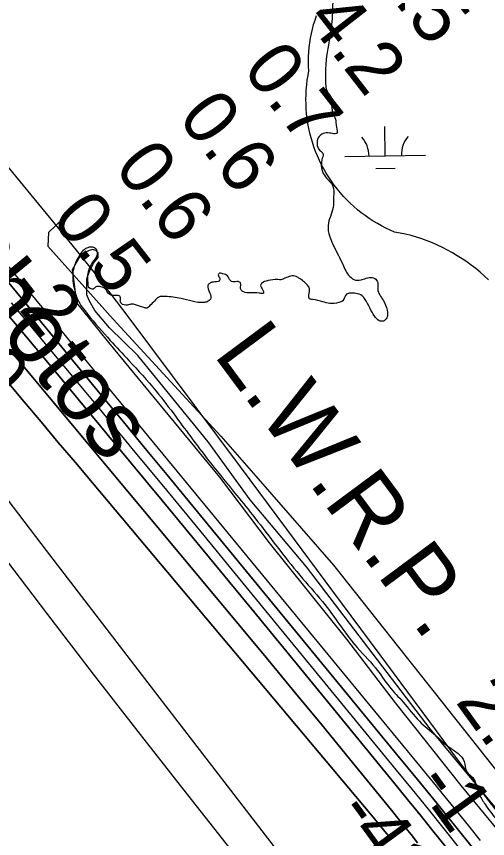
# Model space of a CAD drawing. Extents: x 3887375 to 3925618, y 296674 to 322633.
# Drawn here: x 3902961 to 3903543, y 304360 to 305377 of the extents above; entities that cross this region are included whole.
import ezdxf

# ---------------------------------------------------------------- set-up
doc = ezdxf.new("R2010")
doc.units = 0
for name, color, linetype in [('V-RIVR-EDGE', 7, 'Continuous'), ('V-RIVR-IDEN', 7, 'Continuous'), ('V-RIVR-JETY', 7, 'Continuous'), ('V-RIVR-RANG', 7, 'Continuous'), ('V-RRAP-FSHR', 7, 'Continuous'), ('V-TOPO-DPTH', 7, 'Continuous'), ('V-TOPO-MAJR', 7, 'Continuous'), ('V-TOPO-MINR', 7, 'Continuous'), ('V-TOPO-WATR', 7, 'Continuous'), ('V-TOPO-WATR-IDEN', 7, 'Continuous'), ('V-WETL-SWMP', 7, 'Continuous')]:
    doc.layers.add(name, color=color, linetype=linetype)

msp = doc.modelspace()

# ---------------------------------------------------------------- linework, layer by layer
at = {"layer": 'V-RIVR-EDGE'}
for points in [[(3902176.1, 306371.6), (3902185, 306369.6), (3902189.7, 306365.9), (3902193.6, 306361.3), (3902196.3, 306361.6), (3902200.6, 306361.9), (3902204.3, 306360.9), (3902204.3, 306357.2), (3902207.3, 306355.6), (3902212.9, 306354.6), (3902217.3, 306359.2), (3902217.3, 306360.5), (3902213.9, 306363.5), (3902204.6, 306365.9), (3902201.3, 306370.2), (3902201.3, 306373.6), (3902205.7, 306381.2), (3902209, 306387.2), (3902211.7, 306394.8), (3902215, 306395.8), (3902221, 306396.4), (3902222, 306399.8), (3902220.7, 306414.7), (3902221.1, 306419.4), (3902225.4, 306424.4), (3902235.1, 306431.3), (3902247, 306436.6), (3902261.7, 306439.6), (3902272.3, 306437.9), (3902296.6, 306433.2), (3902307.2, 306432.8), (3902316.2, 306434.8), (3902320.2, 306439.4), (3902328.5, 306449.1), (3902337.9, 306464.7), (3902350.2, 306483.9), (3902359.2, 306492.2), (3902372.6, 306502.5), (3902375.2, 306502.5), (3902376.9, 306498.8), (3902382.5, 306484.2), (3902385.5, 306480.5), (3902388.5, 306484.5), (3902395.2, 306492.1), (3902402.2, 306498.1), (3902406.5, 306498.1), (3902416.4, 306494.7), (3902425.7, 306492.7), (3902437, 306489), (3902445.3, 306479.7), (3902451, 306477), (3902457.3, 306474), (3902462.6, 306472), (3902470.2, 306468), (3902482.5, 306458.3), (3902494.5, 306448), (3902501.8, 306438.3), (3902514, 306428.3), (3902524, 306421), (3902532.6, 306417.3), (3902535.6, 306415.3), (3902527.9, 306397.7), (3902521.6, 306372.8), (3902519.5, 306360.1), (3902521.5, 306352.8), (3902521.8, 306344.8), (3902522.1, 306341.8), (3902524.1, 306339.2), (3902527.5, 306337.8), (3902534.1, 306337.5), (3902538.4, 306337.1), (3902544.1, 306335.1), (3902544.1, 306328.5), (3902550, 306324.1), (3902556.3, 306322.5), (3902561.7, 306323.1), (3902565, 306325.8), (3902570, 306331.4), (3902572, 306338.1), (3902571.7, 306347), (3902569.1, 306353.7), (3902571.4, 306357.7), (3902575.4, 306360.3), (3902579.1, 306361.3), (3902585, 306359), (3902592.7, 306351.3), (3902593, 306344.6), (3902587.3, 306334.7), (3902586.3, 306329.4), (3902585.9, 306322.7), (3902585.6, 306318.1), (3902584.3, 306315.7), (3902576.9, 306316.4), (3902574.9, 306314.8), (3902570.3, 306307.1), (3902569.3, 306302.1), (3902570.6, 306294.5), (3902573.9, 306286.5), (3902577.5, 306281.5), (3902577.2, 306273.5), (3902576.8, 306261.9), (3902576.8, 306255.9), (3902580.1, 306248.6), (3902588.1, 306240.9), (3902593, 306234.6), (3902597.7, 306226.6), (3902598.6, 306211.6), (3902599.6, 306207.6), (3902602.9, 306206.6), (3902607.6, 306205.6), (3902613.2, 306202.9), (3902623.5, 306192.6), (3902623.8, 306183), (3902620.8, 306150), (3902617.1, 306141.7), (3902604.4, 306129.5), (3902600.8, 306128.8), (3902599.1, 306130.8), (3902593.8, 306134.8), (3902592.1, 306134.5), (3902588.1, 306132.8), (3902583.1, 306122.9), (3902581.8, 306112.9), (3902576.8, 306107.3), (3902571.4, 306106.3), (3902567.1, 306105.6), (3902564.8, 306102.3), (3902562.8, 306096), (3902564.4, 306088.7), (3902565.1, 306077.7), (3902563, 306067.4), (3902556.4, 306058.1), (3902540, 306049.2), (3902533, 306041.5), (3902530, 306032.2), (3902526, 306031.2), (3902511.7, 306032.3), (3902507.7, 306031.9), (3902504.1, 306028.6), (3902498.1, 306024.3), (3902498.1, 306022.7), (3902499.4, 306019.7), (3902509.7, 306013), (3902517, 306003), (3902523.3, 305984.4), (3902524.9, 305962.4), (3902516.8, 305945.5), (3902499.8, 305928.2), (3902495.2, 305921.6), (3902491.8, 305915.3), (3902491.5, 305907.9), (3902495.1, 305898), (3902507.7, 305881.6), (3902519, 305871), (3902537.2, 305860), (3902548.9, 305856.6), (3902563.1, 305845.3), (3902578.7, 305830.6), (3902592.7, 305812.9), (3902609.9, 305797.9), (3902620.5, 305791.2), (3902627.5, 305791.6), (3902638.2, 305797.8), (3902653.2, 305812.1), (3902657.9, 305821.4), (3902666.2, 305828.7), (3902675.2, 305837.7), (3902677.5, 305839.7), (3902680.9, 305839.3), (3902680.8, 305837.3), (3902674.8, 305825), (3902672.8, 305820), (3902672.8, 305811.7), (3902671.8, 305803.1), (3902668.4, 305797.8), (3902666.1, 305790.8), (3902666.8, 305785.8), (3902670.4, 305780.8), (3902675.7, 305776.1), (3902679, 305767.2), (3902680.7, 305758.8), (3902685.3, 305754.2), (3902689.6, 305753.2), (3902695.6, 305752.8), (3902700.9, 305748.1), (3902702.9, 305740.2), (3902701.5, 305733.8), (3902694.5, 305721.2), (3902692.2, 305715.6), (3902692.2, 305711.6), (3902693.1, 305701.6), (3902699.4, 305695.3), (3902708.1, 305687.3), (3902714.4, 305676.6), (3902720, 305665.6), (3902725.6, 305651.3), (3902730.9, 305645.3), (3902741.9, 305639), (3902754.8, 305636.6), (3902765.1, 305633.3), (3902768.8, 305628.9), (3902768.8, 305618), (3902768.7, 305611), (3902772.7, 305603.3), (3902781.7, 305599.6), (3902789, 305599.3), (3902796, 305603.6), (3902803, 305605.6), (3902808.3, 305603.9), (3902808.3, 305598.9), (3902804.9, 305594.3), (3902804.9, 305590.3), (3902807.6, 305587.9), (3902817.6, 305583.9), (3902819.6, 305586.2), (3902819.6, 305590.9), (3902821.2, 305591.9), (3902832.5, 305592.5), (3902842.5, 305596.8), (3902852.5, 305597.1), (3902854.8, 305594.8), (3902857.8, 305588.1), (3902865.4, 305585.1), (3902874.1, 305584.8), (3902880.4, 305584.8), (3902884.4, 305580.8), (3902889.7, 305574.1), (3902894.3, 305573.4), (3902905.3, 305571.7), (3902914.3, 305567.1), (3902916.9, 305564.1), (3902916.9, 305558.7), (3902913.2, 305551.8), (3902914.2, 305547.8), (3902915.6, 305542.8), (3902919.5, 305539.8), (3902947.8, 305531.4), (3902977.7, 305524), (3902984.3, 305525), (3902990, 305526.6), (3902996, 305526.3), (3903002, 305519.6), (3903010.9, 305512.6), (3903019.9, 305512.3), (3903025.9, 305511.9), (3903032.2, 305512.2), (3903042.2, 305508.9), (3903061.4, 305496.9), (3903085.3, 305489.1), (3903128.2, 305479.4), (3903164.8, 305476), (3903184.4, 305477.6), (3903213.4, 305483.5), (3903240.3, 305495.1), (3903274, 305520.9), (3903309.3, 305542.8), (3903337.6, 305555), (3903351.2, 305558.3), (3903361.2, 305558.3), (3903371.2, 305555.3), (3903391.7, 305535.6), (3903408, 305512.6), (3903409.6, 305502.3), (3903410.6, 305494.3), (3903401.6, 305487.7), (3903390.2, 305472.1), (3903369.9, 305431.9), (3903356.5, 305407), (3903353.5, 305400), (3903351.8, 305393.4), (3903351.5, 305385.7), (3903349, 305356.1), (3903343.3, 305318.6), (3903342.9, 305298), (3903346.2, 305282), (3903350.8, 305274), (3903350.2, 305270), (3903350.8, 305263.4), (3903351.8, 305257.7), (3903355.1, 305250.1), (3903356.4, 305240.1), (3903356.4, 305232.4), (3903353.4, 305232.1), (3903345.8, 305233.1), (3903338.4, 305231.5), (3903333.8, 305226.8), (3903332.4, 305219.8), (3903335.7, 305211.5), (3903340, 305206.9), (3903339.4, 305203.5), (3903338, 305197.2), (3903338.3, 305187.6), (3903343, 305178.6), (3903351.9, 305167.3), (3903352.9, 305154), (3903352.2, 305140.7), (3903346.1, 305118.7), (3903353.1, 305092.8), (3903364.3, 305070.5), (3903372.9, 305055.5), (3903379.9, 305051.1), (3903389.5, 305052.1), (3903403.8, 305053.1), (3903407.5, 305048.1), (3903407.5, 305039.8), (3903414.1, 305026.1), (3903419, 305013.8), (3903419, 305005.1), (3903416.7, 305001.8), (3903413.7, 305000.2), (3903409.4, 305000.8), (3903403.7, 305006.2), (3903391.8, 305027.2), (3903388.2, 305031.5), (3903380.5, 305034.5), (3903373.9, 305034.9), (3903368.9, 305033.5), (3903364.2, 305025.6), (3903359.2, 305023.3), (3903348.2, 305022.3), (3903339.6, 305024.3), (3903327, 305027), (3903323.3, 305028), (3903322.3, 305032.7), (3903323, 305040.6), (3903320.7, 305044.6), (3903310.1, 305053.6), (3903306.7, 305055.6), (3903292.8, 305053.3), (3903287.8, 305051.4), (3903283.8, 305051.7), (3903271.8, 305050.4), (3903263.8, 305046.8), (3903262.8, 305045.4), (3903264.5, 305040.1), (3903266.1, 305034.8), (3903261.8, 305034.8), (3903247.8, 305035.2), (3903239.9, 305037.5), (3903237.9, 305040.8), (3903237.9, 305047.5), (3903234.9, 305049.2), (3903228.2, 305048.9), (3903225.3, 305050.5), (3903221.6, 305056.2), (3903216, 305058.9), (3903211, 305058.9), (3903210.3, 305057.5), (3903212.3, 305052.9), (3903211.6, 305049.9), (3903208.3, 305048.9), (3903200.6, 305047.6), (3903197.6, 305044.6), (3903199.9, 305035), (3903200.6, 305027.6), (3903196.6, 305024.3), (3903191.9, 305023.3), (3903164.3, 305028.4), (3903144.7, 305030.8), (3903136.8, 305030.1), (3903131.4, 305025.1), (3903125.8, 305019.5), (3903121.8, 305016.5), (3903118.1, 305017.2), (3903108.1, 305020.5), (3903102.5, 305021.2), (3903098.2, 305020.2), (3903090.5, 305022.3), (3903089.2, 305025.9), (3903089.2, 305030.2), (3903087.9, 305031.6), (3903081.6, 305031.9), (3903074.6, 305034.6), (3903070.6, 305040.3), (3903065, 305042.9), (3903059, 305042.6), (3903055.6, 305040), (3903050.7, 305041.6), (3903049.3, 305047.6), (3903049.4, 305059.6), (3903055.1, 305073.2), (3903060.7, 305081.9), (3903060.7, 305086.5), (3903057.8, 305090.5), (3903052.4, 305091.8), (3903045.8, 305089.5), (3903036.4, 305077.9), (3903031.1, 305064.3), (3903030.4, 305053.3), (3903032, 305041.4), (3903036.6, 305026.7), (3903048.6, 305009.1), (3903076.8, 304976.4)], [(3903076.8, 304976.4), (3903099.6, 304951.7), (3903133.5, 304913.7), (3903157.3, 304882.8), (3903201.1, 304824.5), (3903232.9, 304785.1), (3903255.5, 304757.1), (3903311.1, 304686.2), (3903339, 304653.5), (3903361.5, 304623.5), (3903379.1, 304600.2), (3903404.6, 304571.6), (3903422.2, 304547.9), (3903438.8, 304529.2), (3903459, 304505.6), (3903478.9, 304488.2), (3903495.2, 304473.9), (3903506.8, 304465.6), (3903514.4, 304455.6), (3903517.7, 304442.9), (3903525, 304435.9), (3903528, 304430.3), (3903533.3, 304414.6), (3903540.6, 304402.3), (3903553.8, 304385), (3903573.4, 304364.3), (3903587.6, 304346.3), (3903597.9, 304330), (3903605.9, 304324), (3903619.5, 304318), (3903629.1, 304317.6), (3903632.8, 304318.3), (3903633.1, 304320.9), (3903633.5, 304324.3), (3903630.5, 304325.9), (3903622.8, 304326.6), (3903615.5, 304329.9), (3903606.2, 304338.3), (3903597.6, 304350.3), (3903589.3, 304364.3), (3903583.7, 304377.9), (3903578.4, 304391.9), (3903578.4, 304392.9), (3903580.1, 304393.2), (3903589.4, 304383.2), (3903599.7, 304368.6), (3903605.3, 304364.9), (3903612.6, 304364.2), (3903629.3, 304364.8), (3903634.2, 304366.5), (3903638.2, 304368.1), (3903639.3, 304373.8), (3903643.6, 304377.4), (3903648.9, 304379.1), (3903661.2, 304376.4), (3903666.5, 304381.4), (3903670.9, 304383.3), (3903678.8, 304383), (3903682.5, 304380.3), (3903681.5, 304372.3), (3903684.5, 304369.3), (3903690.1, 304365), (3903701.4, 304362), (3903712.4, 304361.6), (3903722, 304361.9), (3903727, 304360.6), (3903733, 304354.3), (3903743.6, 304342.3), (3903751.2, 304323), (3903759.5, 304308.6), (3903773.7, 304295.6), (3903789, 304280.3), (3903789.3, 304273.7), (3903788.3, 304266.7), (3903788.6, 304258), (3903792.2, 304248), (3903804.2, 304230.1), (3903817.7, 304208.1), (3903825.4, 304197.7), (3903828.4, 304195.1), (3903832.7, 304194.4), (3903838, 304199.4), (3903840, 304194.7), (3903840.6, 304188.7), (3903836.6, 304174.4), (3903836.3, 304162.1), (3903833.9, 304151.2), (3903823.2, 304132.6), (3903817.9, 304125.6), (3903807.2, 304122.3), (3903805.2, 304120.6), (3903803.2, 304116), (3903802.8, 304100.7), (3903801.2, 304098.7), (3903799.5, 304102), (3903789.9, 304117.7), (3903782.3, 304126.7), (3903774.7, 304132), (3903768, 304139), (3903763.1, 304152.3), (3903763.1, 304158), (3903770.8, 304167)]]:
    msp.add_spline(points, degree=3, dxfattribs=at)
at = {"layer": 'V-RIVR-JETY'}
msp.add_lwpolyline([(3903654.5, 304276.3), (3903472.4, 304496.3), (3903319.6, 304696.6), (3903249.6, 304779.3), (3903197.8, 304851.1), (3903110.9, 304957.6), (3903075.9, 304992.2), (3903057.6, 305013.3), (3903050.6, 305025.9), (3903047.8, 305032.9), (3903047.8, 305046.9), (3903047.8, 305052.5), (3903050.6, 305060.9), (3903056.2, 305072.1), (3903061.8, 305079.1), (3903061.8, 305084.7), (3903059, 305087.5), (3903054.8, 305088.9), (3903050.6, 305087.5), (3903040.8, 305083.3), (3903029.6, 305063.7), (3903032.4, 305042.7), (3903035.2, 305023.1), (3903050.6, 305003.5), (3903074.5, 304974), (3903105.3, 304936.2), (3903211.8, 304807.3), (3903273.4, 304726), (3903368.7, 304606.9), (3903428.9, 304528.5), (3903510.2, 304426.2), (3903608.3, 304307.1)], dxfattribs=at)
at = {"layer": 'V-RRAP-FSHR'}
msp.add_lwpolyline([(3903045.7, 305153), (3903000.5, 305110.1), (3902999.7, 305092.9), (3903080.3, 305002.7), (3903213.4, 304858.1), (3903256.6, 304808.5), (3903352.6, 304698.4), (3903593.7, 304394.4), (3903689.6, 304280), (3903700.5, 304276.3), (3903747.8, 304312.8)], dxfattribs=at)
at = {"layer": 'V-TOPO-DPTH'}
for points in [[(3903859.2, 304002.2), (3903567.5, 304378.2), (3903545.4, 304406.9), (3903523.4, 304435.6), (3903501.7, 304464.5), (3903480.1, 304493.5), (3903409.1, 304589.4), (3903352.1, 304666.3), (3903295, 304743.2), (3903237.7, 304820), (3903180.4, 304896.8), (3903098.9, 305005.9), (3903077.9, 305033.5), (3903056.7, 305060.9), (3903035.1, 305088.1), (3903013.2, 305115), (3902805.9, 305366.7)], [(3903527.5, 304345.9), (3903504, 304375.1), (3903480.4, 304404.3), (3903456.7, 304433.4), (3903432.9, 304462.5), (3903146.9, 304810.5), (3903120.1, 304843), (3903093.3, 304875.6), (3903066.5, 304908.1), (3903039.6, 304940.6), (3903036, 304944.9), (3903011, 304975.3), (3902985.9, 305005.6), (3902960.8, 305036), (3902935.7, 305066.3)], [(3902935.7, 305066.3), (3902960.8, 305036), (3902985.9, 305005.6), (3903011, 304975.3), (3903036, 304944.9), (3903039.6, 304940.6), (3903066.5, 304908.1), (3903093.3, 304875.6), (3903120.1, 304843), (3903146.9, 304810.5), (3903432.9, 304462.5), (3903456.7, 304433.4), (3903480.4, 304404.3), (3903504, 304375.1), (3903527.5, 304345.9)], [(3902948.6, 305010.1), (3902965.6, 304989.7), (3902982.5, 304969.4), (3902999.4, 304949), (3903082.6, 304848.9), (3903141, 304778.3), (3903199.3, 304707.8), (3903257.5, 304637), (3903315.6, 304566.2), (3903428.6, 304428.3), (3903444.3, 304408.9), (3903460, 304389.6), (3903475.7, 304370.1), (3903491.3, 304350.7)], [(3902948.6, 305010.1), (3902965.6, 304989.7), (3902982.5, 304969.4), (3902999.4, 304949), (3903082.6, 304848.9), (3903141, 304778.3), (3903199.3, 304707.8), (3903257.5, 304637), (3903315.6, 304566.2), (3903428.6, 304428.3), (3903444.3, 304408.9), (3903460, 304389.6), (3903475.7, 304370.1), (3903491.3, 304350.7)], [(3903456.7, 304355.3), (3903448.7, 304365.4), (3903440.6, 304375.5), (3903432.5, 304385.5), (3903424.4, 304395.5), (3903372.4, 304459.2), (3903338.2, 304501), (3903303.9, 304542.7), (3903269.5, 304584.3), (3903235, 304625.8), (3902961.9, 304953.1), (3902953.4, 304963.3)], [(3902953.4, 304963.3), (3902961.9, 304953.1), (3903235, 304625.8), (3903269.5, 304584.3), (3903303.9, 304542.7), (3903338.2, 304501), (3903372.4, 304459.2), (3903424.4, 304395.5), (3903432.5, 304385.5), (3903440.6, 304375.5), (3903448.7, 304365.4), (3903456.7, 304355.3)], [(3903423.8, 304359.8), (3903422.1, 304362), (3903421.2, 304363.1), (3903420.3, 304364.1), (3903414.6, 304371.2), (3903410.9, 304375.7), (3903407.1, 304380.3), (3903403.4, 304384.9), (3903399.6, 304389.4), (3903054.7, 304800.2), (3903033.6, 304825.3), (3903012.5, 304850.4), (3902991.3, 304875.6), (3902970.2, 304900.7), (3902930.2, 304948)], [(3902930.2, 304948), (3902970.2, 304900.7), (3902991.3, 304875.6), (3903012.5, 304850.4), (3903033.6, 304825.3), (3903054.7, 304800.2), (3903399.6, 304389.4), (3903403.4, 304384.9), (3903407.1, 304380.3), (3903410.9, 304375.7), (3903414.6, 304371.2), (3903420.3, 304364.1), (3903421.2, 304363.1), (3903422.1, 304362), (3903423.8, 304359.8)]]:
    msp.add_lwpolyline(points, dxfattribs=at)
at = {"layer": 'V-TOPO-MAJR'}
msp.add_lwpolyline([(3903314.6, 304305.1), (3903141.4, 304530), (3903093.6, 304592.1), (3903045.8, 304654.3), (3902998.1, 304716.5), (3902950.4, 304778.8)], dxfattribs=at)
at = {"layer": 'V-TOPO-MINR'}
for points in [[(3903534.5, 304358.1), (3903520, 304376.1), (3903505.5, 304394.1), (3903491, 304412.1), (3903476.4, 304429.9), (3903461.7, 304447.8), (3903061.4, 304933.9), (3903050.5, 304947.2), (3903039.6, 304960.5), (3903028.6, 304973.7), (3903017.7, 304986.9), (3903001.3, 305006.8), (3902998.6, 305010.1), (3902995.9, 305013.4), (3902993.2, 305016.7), (3902990.4, 305020.1), (3902584.2, 305513.2)], [(3903527.5, 304345.9), (3903504, 304375.1), (3903480.4, 304404.3), (3903456.7, 304433.4), (3903432.9, 304462.5), (3903146.9, 304810.5), (3903120.1, 304843), (3903093.3, 304875.6), (3903066.5, 304908.1), (3903039.6, 304940.6), (3903036, 304944.9), (3903011, 304975.3), (3902985.9, 305005.6), (3902960.8, 305036), (3902935.7, 305066.3)], [(3903509.2, 304348.3), (3903489.7, 304372.6), (3903470.1, 304396.9), (3903450.4, 304421), (3903430.7, 304445.2), (3903231.6, 304687.9), (3903189.1, 304739.6), (3903146.5, 304791.3), (3903103.9, 304843), (3903061.2, 304894.6), (3903017.8, 304947), (3902996.8, 304972.3), (3902975.8, 304997.7), (3902954.7, 305023.1)], [(3903491.3, 304350.7), (3903475.7, 304370.1), (3903460, 304389.6), (3903444.3, 304408.9), (3903428.6, 304428.3), (3903315.6, 304566.2), (3903257.5, 304637), (3903199.3, 304707.8), (3903141, 304778.3), (3903082.6, 304848.9), (3902999.4, 304949), (3902982.5, 304969.4), (3902965.6, 304989.7), (3902948.6, 305010.1)], [(3903456.7, 304355.3), (3903448.7, 304365.4), (3903440.6, 304375.5), (3903432.5, 304385.5), (3903424.4, 304395.5), (3903372.4, 304459.2), (3903338.2, 304501), (3903303.9, 304542.7), (3903269.5, 304584.3), (3903235, 304625.8), (3902961.9, 304953.1), (3902953.4, 304963.3)], [(3903423.8, 304359.8), (3903422.1, 304362), (3903421.2, 304363.1), (3903420.3, 304364.1), (3903414.6, 304371.2), (3903410.9, 304375.7), (3903407.1, 304380.3), (3903403.4, 304384.9), (3903399.6, 304389.4), (3903054.7, 304800.2), (3903033.6, 304825.3), (3903012.5, 304850.4), (3902991.3, 304875.6), (3902970.2, 304900.7), (3902930.2, 304948)], [(3904127.3, 303194.1), (3904081.2, 303256), (3904035, 303317.7), (3903846.7, 303567.3), (3903832.7, 303585.6), (3903818.6, 303603.9), (3903804.4, 303622.1), (3903790.1, 303640.2), (3903704.2, 303747.7), (3903646.9, 303819.5), (3903589.5, 303891.2), (3903532.2, 303963), (3903474.8, 304034.7), (3903327.7, 304218.3), (3903308.7, 304242.1), (3903289.8, 304265.9), (3903270.9, 304289.7), (3903252.1, 304313.6), (3903172.5, 304414.6), (3903114.1, 304489.1), (3903056.1, 304563.9), (3902998.5, 304639.1), (3902941.2, 304714.5)]]:
    msp.add_lwpolyline(points, dxfattribs=at)
at = {"layer": 'V-TOPO-WATR'}
msp.add_lwpolyline([(3903859.2, 304002.2), (3903567.5, 304378.2), (3903545.4, 304406.9), (3903523.4, 304435.6), (3903501.7, 304464.5), (3903480.1, 304493.5), (3903409.1, 304589.4), (3903352.1, 304666.3), (3903295, 304743.2), (3903237.7, 304820), (3903180.4, 304896.8), (3903098.9, 305005.9), (3903077.9, 305033.5), (3903056.7, 305060.9), (3903035.1, 305088.1), (3903013.2, 305115), (3902805.9, 305366.7)], dxfattribs=at)
at = {"layer": 'V-WETL-SWMP'}
for p, q in [((3903330, 305372.6), (3903331.9, 305378.1)), ((3903326.7, 305361.5), (3903328.2, 305367.1)), ((3903328.2, 305367.1), (3903330, 305372.6)), ((3903325.4, 305355.9), (3903326.7, 305361.5)), ((3903323.4, 305344.5), (3903324.3, 305350.2)), ((3903324.3, 305350.2), (3903325.4, 305355.9)), ((3903322.2, 305333.1), (3903322.7, 305338.8)), ((3903322.7, 305338.8), (3903323.4, 305344.5)), ((3903321.9, 305327.3), (3903322.2, 305333.1)), ((3903321.9, 305321.5), (3903321.9, 305327.3)), ((3903322, 305315.7), (3903321.9, 305321.5)), ((3903321.3, 305304.1), (3903322.4, 305310)), ((3903322.4, 305310), (3903322, 305315.7)), ((3903319.7, 305292.3), (3903320.4, 305298.2)), ((3903320.4, 305298.2), (3903321.3, 305304.1)), ((3903318.8, 305280.3), (3903319.1, 305286.3)), ((3903319.1, 305286.3), (3903319.7, 305292.3)), ((3903318.7, 305274.4), (3903318.8, 305280.3)), ((3903318.8, 305268.4), (3903318.7, 305274.4)), ((3903319.1, 305262.4), (3903318.8, 305268.4)), ((3903319.6, 305256.5), (3903319.1, 305262.4)), ((3903320.3, 305250.5), (3903319.6, 305256.5)), ((3903321.2, 305244.6), (3903320.3, 305250.5)), ((3903322.3, 305238.7), (3903321.2, 305244.6)), ((3903323.6, 305232.9), (3903322.3, 305238.7)), ((3903416.7, 305204.8), (3903416.1, 305240.8)), ((3903325.1, 305227.1), (3903323.6, 305232.9)), ((3903326.8, 305221.4), (3903325.1, 305227.1)), ((3903328.6, 305215.7), (3903326.8, 305221.4)), ((3903330.7, 305210.1), (3903328.6, 305215.7)), ((3903333, 305204.6), (3903330.7, 305210.1)), ((3903335.4, 305199.1), (3903333, 305204.6)), ((3903366.7, 305204), (3903466.7, 305205.7)), ((3903338, 305193.7), (3903335.4, 305199.1)), ((3903340.8, 305188.5), (3903338, 305193.7)), ((3903343.8, 305183.3), (3903340.8, 305188.5)), ((3903405, 305189.2), (3903429, 305189.6)), ((3903347, 305178.2), (3903343.8, 305183.3)), ((3903350.3, 305173.2), (3903347, 305178.2)), ((3903353.8, 305168.4), (3903350.3, 305173.2)), ((3903357.4, 305163.7), (3903353.8, 305168.4)), ((3903361.3, 305159.1), (3903357.4, 305163.7)), ((3903365.2, 305154.6), (3903361.3, 305159.1)), ((3903369.3, 305150.3), (3903365.2, 305154.6)), ((3903373.6, 305146.1), (3903369.3, 305150.3)), ((3903378, 305142), (3903373.6, 305146.1)), ((3903382.5, 305138.1), (3903378, 305142)), ((3903387.2, 305134.4), (3903382.5, 305138.1)), ((3903392, 305130.8), (3903387.2, 305134.4)), ((3903396.9, 305127.4), (3903392, 305130.8)), ((3903401.9, 305124.1), (3903396.9, 305127.4)), ((3903407, 305121), (3903401.9, 305124.1)), ((3903412.2, 305118.1), (3903407, 305121)), ((3903417.5, 305115.4), (3903412.2, 305118.1)), ((3903423, 305112.9), (3903417.5, 305115.4)), ((3903428.4, 305110.5), (3903423, 305112.9)), ((3903435.3, 305109.2), (3903428.4, 305110.5)), ((3903442, 305107.7), (3903435.3, 305109.2)), ((3903448.8, 305106), (3903442, 305107.7)), ((3903455.4, 305104), (3903448.8, 305106)), ((3903462, 305101.9), (3903455.4, 305104)), ((3903468.6, 305099.5), (3903462, 305101.9)), ((3903475, 305097), (3903468.6, 305099.5)), ((3903481.4, 305094.2), (3903475, 305097)), ((3903487.7, 305091.2), (3903481.4, 305094.2)), ((3903493.9, 305088.1), (3903487.7, 305091.2)), ((3903500, 305084.7), (3903493.9, 305088.1)), ((3903505.9, 305081.2), (3903500, 305084.7)), ((3903511.8, 305077.5), (3903505.9, 305081.2)), ((3903517.5, 305073.6), (3903511.8, 305077.5)), ((3903523.2, 305069.5), (3903517.5, 305073.6)), ((3903528.6, 305065.3), (3903523.2, 305069.5)), ((3903534, 305060.8), (3903528.6, 305065.3)), ((3903539.2, 305056.2), (3903534, 305060.8)), ((3903544.3, 305051.5), (3903539.2, 305056.2))]:
    msp.add_line(p, q, dxfattribs=at)
for centre, start, end in [((3903361.5, 305204.3), 0.2115, 41.7552), ((3903472, 305206.2), 140.2115, 181.7552)]:
    msp.add_arc(centre, 35.2, start, end, dxfattribs=at)

# ---------------------------------------------------------------- texts
at = {"layer": 'V-RIVR-IDEN'}
msp.add_text('Aerial    Photos', height=83, rotation=309.2735, dxfattribs=at).set_placement((3902596.7, 305405.2))
at = {"layer": 'V-RIVR-RANG'}
for s, rotation, p in [('4.5', 307.8683, (3903396.5, 305435.1)), ('4.2', 307.8683, (3903317.7, 305373.5)), ('0.7', 307.8683, (3903238.9, 305311.9)), ('0.6', 307.8683, (3903159, 305251.8)), ('0.6', 307.8683, (3903080.2, 305190.2)), ('0.5', 307.8683, (3903002.5, 305127.2)), ('-2', 307.8683, (3902944.3, 305039.2)), ('-40', 308.1531, (3902848.6, 304998.7)), ('2.0', 305.8583, (3903502.7, 304529.9)), ('-1', 305.8583, (3903452.9, 304428.2)), ('-41', 306.14, (3903354.8, 304392.6))]:
    msp.add_text(s, height=67, rotation=rotation, dxfattribs=at).set_placement(p)
at = {"layer": 'V-TOPO-WATR-IDEN'}
msp.add_text('L.W.R.P.', height=83, rotation=306.5935, dxfattribs=at).set_placement((3903203.3, 304959.2))

doc.saveas('drawing.dxf')
